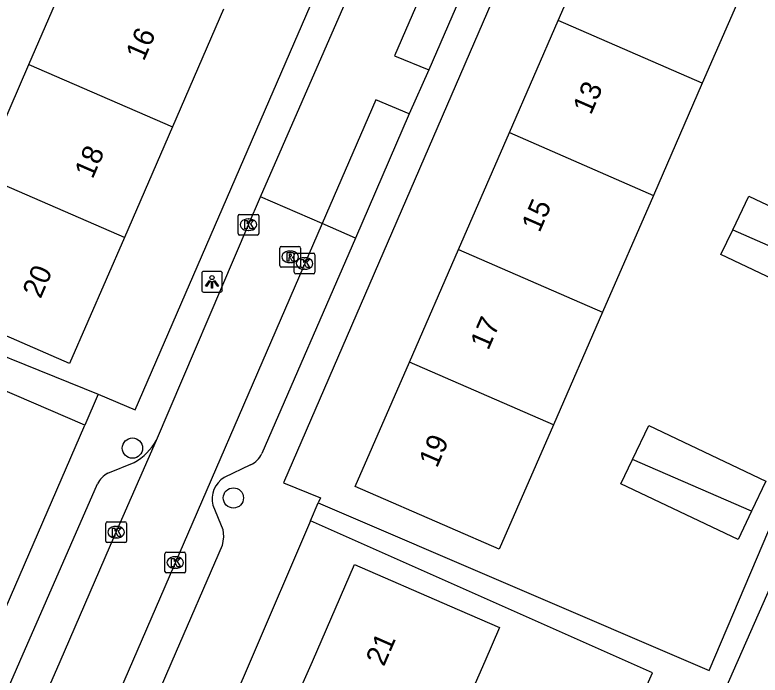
# Model space of a CAD drawing. Extents: x 162812 to 163818, y 381639 to 382470.
# Drawn here: x 163316.9 to 163352.9, y 381999.34 to 382031.25 of the extents above; entities that cross this region are included whole.
import ezdxf

# ---------------------------------------------------------------- set-up
doc = ezdxf.new("R2010")
doc.units = 0
for name, color, linetype in [('IMGEO_Boom', 7, 'Continuous'), ('IMGEO_Kolk', 7, 'Continuous'), ('IMGEO_Lichtpunt', 7, 'Continuous'), ('IMGEO_Pand', 7, 'Continuous'), ('IMGEO_Pand_nummerreeks', 7, 'Continuous'), ('IMGEO_Parkeervlak_open', 7, 'Continuous'), ('IMGEO_Rijbaan_lokaal_open', 7, 'Continuous'), ('IMGEO_Rioolput', 7, 'Continuous'), ('IMGEO_Voetpad_open', 7, 'Continuous')]:
    doc.layers.add(name, color=color, linetype=linetype)

msp = doc.modelspace()

# ---------------------------------------------------------------- linework, layer by layer
at = {"layer": 'IMGEO_Boom'}
for centre in [(163322.577, 382010.31), (163327.453, 382007.9)]:
    msp.add_circle(centre, 0.489, dxfattribs=at)
at = {"layer": 'IMGEO_Kolk'}
for p, q in [((163327.755, 382021.606), (163328.607, 382021.606)), ((163327.68, 382020.68), (163327.68, 382021.532)), ((163328.168, 382021.386), (163328.193, 382021.386)), ((163328.681, 382021.532), (163328.681, 382020.68)), ((163328.607, 382020.606), (163327.755, 382020.606)), ((163328.191, 382020.826), (163328.166, 382020.826)), ((163330.391, 382018.805), (163330.391, 382019.657)), ((163330.466, 382019.731), (163331.318, 382019.731)), ((163330.879, 382019.511), (163330.904, 382019.511)), ((163331.392, 382019.657), (163331.392, 382018.805)), ((163331.318, 382018.731), (163330.466, 382018.731)), ((163330.902, 382018.951), (163330.877, 382018.951)), ((163321.288, 382005.819), (163321.288, 382006.671)), ((163321.363, 382006.745), (163322.215, 382006.745)), ((163321.776, 382006.525), (163321.801, 382006.525)), ((163322.289, 382006.671), (163322.289, 382005.819)), ((163321.799, 382005.965), (163321.774, 382005.965)), ((163322.215, 382005.745), (163321.363, 382005.745)), ((163324.146, 382004.353), (163324.146, 382005.205)), ((163324.221, 382005.279), (163325.073, 382005.279)), ((163324.634, 382005.059), (163324.659, 382005.059)), ((163325.147, 382005.205), (163325.147, 382004.353)), ((163324.657, 382004.499), (163324.632, 382004.499)), ((163325.073, 382004.279), (163324.221, 382004.279))]:
    msp.add_line(p, q, dxfattribs=at)
for points in [[(163327.755, 382021.606), (163328.607, 382021.606)], [(163327.68, 382020.68), (163327.68, 382021.532)], [(163328.001, 382021.306), (163328.124, 382021.306), (163328.124, 382021.155), (163328.254, 382021.306), (163328.418, 382021.306), (163328.272, 382021.155), (163328.425, 382020.906), (163328.273, 382020.906), (163328.188, 382021.07), (163328.124, 382021.003), (163328.124, 382020.906), (163328.001, 382020.906), (163328.001, 382021.306)], [(163328.681, 382021.532), (163328.681, 382020.68)], [(163328.607, 382020.606), (163327.755, 382020.606)], [(163330.391, 382018.805), (163330.391, 382019.657)], [(163330.466, 382019.731), (163331.318, 382019.731)], [(163330.712, 382019.431), (163330.835, 382019.431), (163330.835, 382019.28), (163330.965, 382019.431), (163331.129, 382019.431), (163330.983, 382019.28), (163331.136, 382019.031), (163330.984, 382019.031), (163330.899, 382019.195), (163330.835, 382019.128), (163330.835, 382019.031), (163330.712, 382019.031), (163330.712, 382019.431)], [(163331.392, 382019.657), (163331.392, 382018.805)], [(163331.318, 382018.731), (163330.466, 382018.731)], [(163321.288, 382005.819), (163321.288, 382006.671)], [(163321.363, 382006.745), (163322.215, 382006.745)], [(163322.289, 382006.671), (163322.289, 382005.819)], [(163321.609, 382006.445), (163321.732, 382006.445), (163321.732, 382006.294), (163321.862, 382006.445), (163322.026, 382006.445), (163321.88, 382006.294), (163322.033, 382006.045), (163321.881, 382006.045), (163321.796, 382006.209), (163321.732, 382006.142), (163321.732, 382006.045), (163321.609, 382006.045), (163321.609, 382006.445)], [(163322.215, 382005.745), (163321.363, 382005.745)], [(163324.146, 382004.353), (163324.146, 382005.205)], [(163324.221, 382005.279), (163325.073, 382005.279)], [(163325.147, 382005.205), (163325.147, 382004.353)], [(163324.467, 382004.979), (163324.59, 382004.979), (163324.59, 382004.828), (163324.72, 382004.979), (163324.884, 382004.979), (163324.738, 382004.828), (163324.891, 382004.579), (163324.739, 382004.579), (163324.654, 382004.743), (163324.59, 382004.676), (163324.59, 382004.579), (163324.467, 382004.579), (163324.467, 382004.979)], [(163325.073, 382004.279), (163324.221, 382004.279)]]:
    msp.add_lwpolyline(points, dxfattribs=at)
for centre, start, end in [((163327.757, 382021.53), 91.552, 178.448), ((163327.757, 382021.53), 91.552, 178.448), ((163328.605, 382021.53), 1.552, 88.448), ((163328.605, 382021.53), 1.552, 88.448), ((163327.757, 382020.682), 181.552, 268.448), ((163327.757, 382020.682), 181.552, 268.448), ((163328.605, 382020.682), 271.552, 358.448), ((163328.605, 382020.682), 271.552, 358.448), ((163330.468, 382019.655), 91.552, 178.448), ((163330.468, 382019.655), 91.552, 178.448), ((163331.316, 382019.655), 1.552, 88.448), ((163331.316, 382019.655), 1.552, 88.448), ((163330.468, 382018.807), 181.552, 268.448), ((163330.468, 382018.807), 181.552, 268.448), ((163331.316, 382018.807), 271.552, 358.448), ((163331.316, 382018.807), 271.552, 358.448), ((163321.365, 382006.669), 91.552, 178.448), ((163321.365, 382006.669), 91.552, 178.448), ((163322.213, 382006.669), 1.552, 88.448), ((163322.213, 382006.669), 1.552, 88.448), ((163321.365, 382005.821), 181.552, 268.448), ((163321.365, 382005.821), 181.552, 268.448), ((163322.213, 382005.821), 271.552, 358.448), ((163322.213, 382005.821), 271.552, 358.448), ((163324.223, 382005.203), 91.552, 178.448), ((163324.223, 382005.203), 91.552, 178.448), ((163325.071, 382005.203), 1.552, 88.448), ((163325.071, 382005.203), 1.552, 88.448), ((163324.223, 382004.355), 181.552, 268.448), ((163324.223, 382004.355), 181.552, 268.448), ((163325.071, 382004.355), 271.552, 358.448), ((163325.071, 382004.355), 271.552, 358.448)]:
    msp.add_arc(centre, 0.0765, start, end, dxfattribs=at)
for centre, major_axis, ratio, start_param, end_param in [((163328.167, 382021.106), (-0.387, 0.002), 0.722429, 4.712389, 7.853982), ((163328.192, 382021.106), (-0.39, 0.002), 0.717154, 1.570796, 4.712389), ((163330.878, 382019.231), (-0.387, 0.002), 0.722429, 4.712389, 7.853982), ((163330.903, 382019.231), (-0.39, 0.002), 0.717154, 1.570796, 4.712389), ((163321.775, 382006.245), (-0.387, 0.002), 0.722429, 4.712389, 7.853982), ((163321.8, 382006.245), (-0.39, 0.002), 0.717154, 1.570796, 4.712389), ((163324.633, 382004.779), (-0.387, 0.002), 0.722429, 4.712389, 7.853982), ((163324.658, 382004.779), (-0.39, 0.002), 0.717154, 1.570796, 4.712389)]:
    msp.add_ellipse(centre, major_axis=major_axis, ratio=ratio, start_param=start_param, end_param=end_param, dxfattribs=at)
at = {"layer": 'IMGEO_Lichtpunt'}
for p, q in [((163325.923, 382018.753), (163325.923, 382017.946)), ((163325.923, 382018.753), (163325.923, 382017.946)), ((163326.825, 382018.848), (163326.017, 382018.848)), ((163326.825, 382018.848), (163326.017, 382018.848)), ((163326.919, 382017.946), (163326.919, 382018.753)), ((163326.919, 382017.946), (163326.919, 382018.753)), ((163326.017, 382017.852), (163326.825, 382017.852)), ((163326.017, 382017.852), (163326.825, 382017.852))]:
    msp.add_line(p, q, dxfattribs=at)
for points in [[(163326.297, 382018.417), (163326.336, 382018.389), (163326.148, 382018.127), (163326.11, 382018.154), (163326.297, 382018.417)], [(163326.399, 382018.369), (163326.446, 382018.369), (163326.446, 382018.047), (163326.399, 382018.047), (163326.399, 382018.369)], [(163326.509, 382018.389), (163326.547, 382018.416), (163326.734, 382018.154), (163326.695, 382018.126), (163326.509, 382018.389)]]:
    msp.add_lwpolyline(points, dxfattribs=at)
msp.add_circle((163326.422, 382018.551), 0.0994, dxfattribs=at)
for centre, start, end in [((163326.017, 382018.753), 90, 180), ((163326.017, 382018.753), 90, 180), ((163326.825, 382018.753), 0, 90), ((163326.825, 382018.753), 0, 90), ((163326.017, 382017.946), 180, 270), ((163326.017, 382017.946), 180, 270), ((163326.825, 382017.946), 270, 0), ((163326.825, 382017.946), 270, 360)]:
    msp.add_arc(centre, 0.0946, start, end, dxfattribs=at)
at = {"layer": 'IMGEO_Pand'}
for points in [[(163343.147, 382030.971), (163345.654, 382036.722)], [(163317.567, 382028.844), (163320.041, 382034.537)], [(163352.612, 382033.691), (163350.105, 382027.939)], [(163326.981, 382031.522), (163324.508, 382025.829)], [(163340.787, 382025.555), (163343.147, 382030.971)], [(163350.105, 382027.939), (163343.147, 382030.971)], [(163315.247, 382023.502), (163317.567, 382028.844)], [(163317.567, 382028.844), (163324.508, 382025.829)], [(163350.105, 382027.939), (163347.745, 382022.523)], [(163324.508, 382025.829), (163322.187, 382020.487)], [(163338.328, 382019.913), (163340.787, 382025.555)], [(163340.787, 382025.555), (163347.745, 382022.523)], [(163322.187, 382020.487), (163319.54, 382014.394), (163314.955, 382016.388), (163312.6, 382017.41), (163315.247, 382023.502)], [(163322.187, 382020.487), (163315.247, 382023.502)], [(163347.745, 382022.523), (163345.286, 382016.881)], [(163351.571, 382020.856), (163352.347, 382022.491), (163358.003, 382019.805), (163357.314, 382018.353)], [(163357.314, 382018.353), (163356.662, 382016.981), (163351.006, 382019.667), (163351.571, 382020.856)], [(163351.571, 382020.856), (163357.314, 382018.353)], [(163335.954, 382014.466), (163338.328, 382019.913)], [(163338.328, 382019.913), (163345.286, 382016.881)], [(163345.286, 382016.881), (163342.912, 382011.433)], [(163342.912, 382011.433), (163340.291, 382005.42), (163337.917, 382006.456), (163333.333, 382008.452), (163335.954, 382014.466)], [(163342.912, 382011.433), (163335.954, 382014.466)], [(163346.738, 382009.765), (163347.514, 382011.401), (163353.17, 382008.715), (163352.48, 382007.262)], [(163352.48, 382007.262), (163351.829, 382005.891), (163346.173, 382008.577), (163346.738, 382009.765)], [(163352.48, 382007.262), (163346.738, 382009.765)], [(163330.693, 381998.683), (163331.267, 382000), (163333.309, 382004.685), (163337.893, 382002.688), (163340.308, 382001.635), (163339.592, 382000), (163337.68, 381995.637)]]:
    msp.add_lwpolyline(points, dxfattribs=at)
at = {"layer": 'IMGEO_Parkeervlak_open'}
msp.add_lwpolyline([(163333.345, 382020.461), (163331.738, 382021.158)], dxfattribs=at)
at = {"layer": 'IMGEO_Rijbaan_lokaal_open'}
for points in [[(163328.767, 382022.447), (163334.915, 382036.546)], [(163337.839, 382035.296), (163335.235, 382029.261), (163336.897, 382028.592)], [(163336.897, 382028.592), (163335.951, 382026.465)], [(163335.951, 382026.465), (163334.326, 382027.135), (163331.738, 382021.158)], [(163323.733, 382010.699), (163328.165, 382021.067), (163328.767, 382022.447)], [(163331.738, 382021.158), (163328.767, 382022.447)], [(163331.738, 382021.158), (163322.577, 382000), (163318.052, 381989.55)], [(163315.149, 381991.029), (163316.562, 381994.209), (163319.078, 382000), (163321.729, 382006.103), (163323.733, 382010.699)]]:
    msp.add_lwpolyline(points, dxfattribs=at)
at = {"layer": 'IMGEO_Rioolput'}
for p, q in [((163329.694, 382019.128), (163329.694, 382019.98)), ((163329.769, 382020.054), (163330.621, 382020.054)), ((163330.182, 382019.834), (163330.207, 382019.834)), ((163330.695, 382019.98), (163330.695, 382019.128)), ((163330.205, 382019.274), (163330.18, 382019.274)), ((163330.621, 382019.054), (163329.769, 382019.054))]:
    msp.add_line(p, q, dxfattribs=at)
for points in [[(163329.694, 382019.128), (163329.694, 382019.98)], [(163329.769, 382020.054), (163330.621, 382020.054)], [(163330.695, 382019.98), (163330.695, 382019.128)], [(163330.283, 382019.752), (163330.031, 382019.754), (163330.031, 382019.354)], [(163330.031, 382019.354), (163330.155, 382019.354), (163330.155, 382019.516), (163330.166, 382019.516)], [(163330.209, 382019.673), (163330.155, 382019.673), (163330.155, 382019.592)], [(163330.155, 382019.592), (163330.207, 382019.592)], [(163330.213, 382019.487), (163330.284, 382019.354), (163330.424, 382019.354), (163330.359, 382019.48)], [(163330.621, 382019.054), (163329.769, 382019.054)]]:
    msp.add_lwpolyline(points, dxfattribs=at)
for centre, radius, start, end in [((163329.771, 382019.978), 0.0765, 91.552, 178.448), ((163329.771, 382019.978), 0.0765, 91.552, 178.448), ((163330.619, 382019.978), 0.0765, 1.552, 88.448), ((163330.619, 382019.978), 0.0765, 1.552, 88.448), ((163330.165, 382019.463), 0.0533, 26.0293, 88.6989), ((163330.191, 382019.781), 0.19, 274.7715, 282.9687), ((163330.215, 382019.577), 0.0964, 77.0061, 93.1865), ((163330.229, 382019.634), 0.0378, 276.6634, 79.6772), ((163330.282, 382019.642), 0.109, 350.3612, 89.416), ((163330.28, 382019.642), 0.112, 277.5842, 350.9817), ((163330.264, 382019.427), 0.108, 29.5134, 73.7905), ((163329.771, 382019.13), 0.0765, 181.552, 268.448), ((163329.771, 382019.13), 0.0765, 181.552, 268.448), ((163330.619, 382019.13), 0.0765, 271.552, 358.448), ((163330.619, 382019.13), 0.0765, 271.552, 358.448)]:
    msp.add_arc(centre, radius, start, end, dxfattribs=at)
for centre, major_axis, ratio, start_param, end_param in [((163330.181, 382019.554), (-0.387, 0.002), 0.722429, 4.712389, 7.853982), ((163330.206, 382019.554), (-0.39, 0.002), 0.717154, 1.570796, 4.712389)]:
    msp.add_ellipse(centre, major_axis=major_axis, ratio=ratio, start_param=start_param, end_param=end_param, dxfattribs=at)
at = {"layer": 'IMGEO_Voetpad_open'}
for points in [[(163320.918, 382012.914), (163322.712, 382012.16), (163347.746, 382069.96)], [(163355.059, 382066.816), (163329.868, 382008.632), (163331.655, 382007.908), (163331.551, 382007.665)], [(163339.487, 382034.591), (163336.897, 382028.592)], [(163335.951, 382026.465), (163333.345, 382020.461)], [(163331.551, 382007.665), (163350.436, 381999.565), (163361.097, 382024.652), (163362.402, 382024.064), (163350.573, 381997.224)], [(163333.345, 382020.461), (163328.825, 382010.047)], [(163300.993, 382018.779), (163312.389, 382016.368), (163320.918, 382012.914)], [(163320.27, 382011.419), (163311.944, 382015.003), (163301.925, 382016.594), (163297.498, 382006.743)], [(163320.918, 382012.914), (163320.27, 382011.419)], [(163311.571, 381991.346), (163312.362, 381993.172), (163315.321, 382000), (163320.27, 382011.419)], [(163321.391, 382009.096), (163322.66, 382009.615)], [(163328.287, 382009.504), (163327.009, 382008.896)], [(163314.63, 381994.261), (163317.138, 382000), (163320.889, 382008.583)], [(163331.175, 382006.79), (163331.551, 382007.665)], [(163326.461, 382007.544), (163326.947, 382006.371), (163326.975, 382006.022), (163326.904, 382005.61), (163324.487, 382000), (163320.911, 381991.698), (163320.672, 381991.422), (163320.362, 381991.187), (163319.153, 381990.64)], [(163331.175, 382006.79), (163328.258, 382000), (163323.267, 381988.382), (163322.499, 381986.595)], [(163343.709, 381986.429), (163342.173, 381987.038), (163347.701, 381999.452), (163331.175, 382006.79)]]:
    msp.add_lwpolyline(points, dxfattribs=at)
for centre, radius, start, end in [((163321.439, 382011.897), 2.588, 298.1555, 332.4289), ((163327.873, 382010.452), 1.035, 293.5844, 336.9456), ((163321.949, 382008.048), 1.188, 118.0337, 153.2081), ((163327.658, 382007.846), 1.234, 121.7059, 194.1661)]:
    msp.add_arc(centre, radius, start, end, dxfattribs=at)

# ---------------------------------------------------------------- texts
at = {"layer": 'IMGEO_Pand_nummerreeks'}
for s, rotation, p in [('16', 66.5184, (163323.127, 382028.975)), ('13', 66.4511, (163344.723, 382026.377)), ('18', 66.5184, (163320.652, 382023.277)), ('15', 66.4511, (163342.243, 382020.689)), ('20', 66.5184, (163318.139, 382017.494)), ('17', 66.4511, (163339.764, 382015)), ('19', 66.4511, (163337.285, 382009.312)), ('21', 66.4498, (163334.723, 381999.72))]:
    msp.add_text(s, height=1, rotation=rotation, dxfattribs=at).set_placement(p)

doc.saveas('drawing.dxf')
